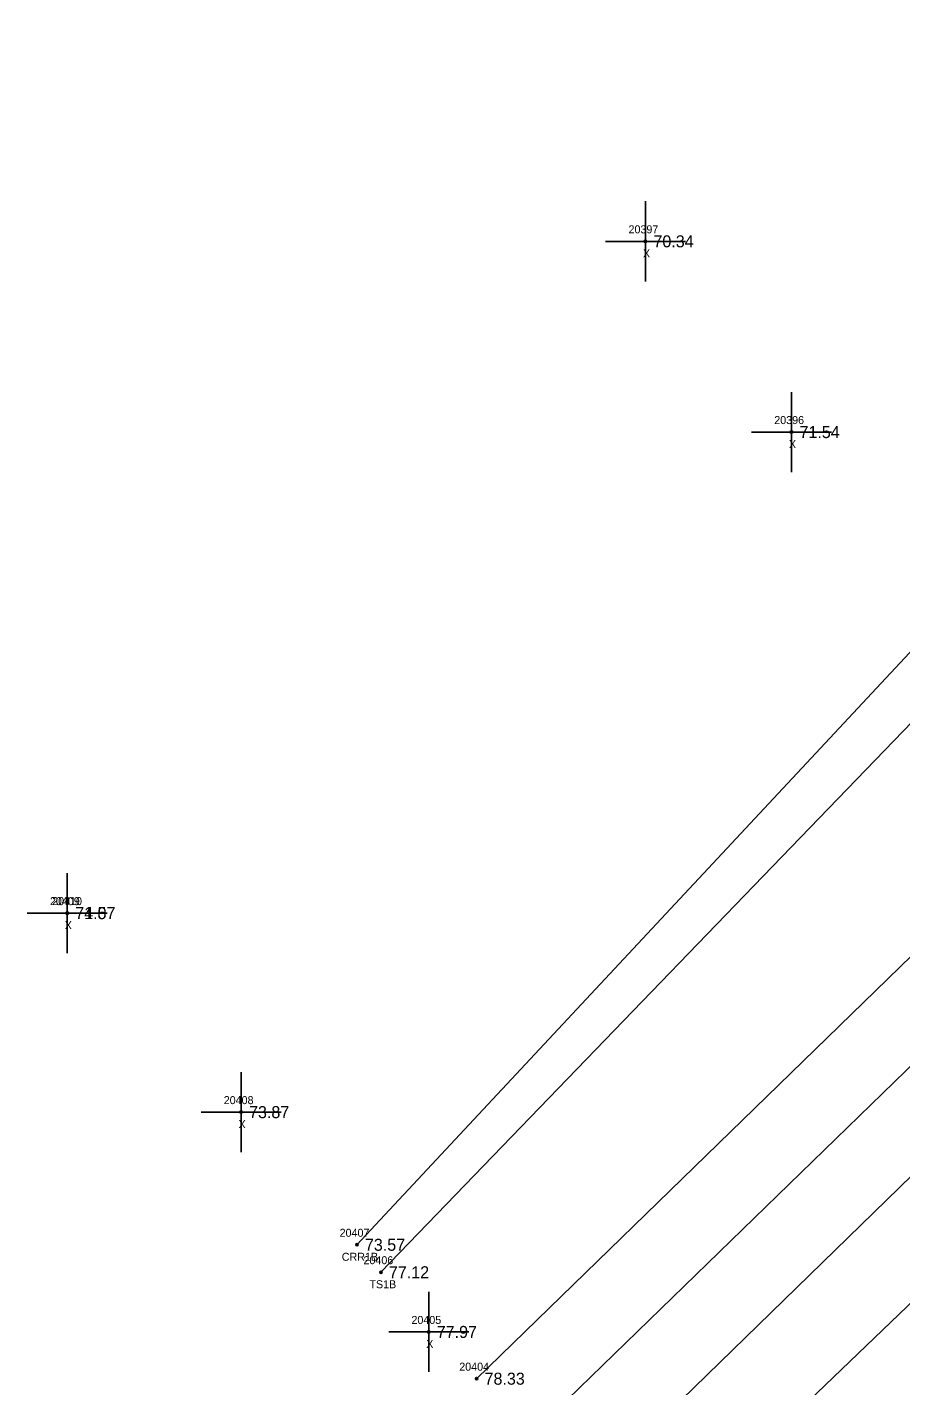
# Model space of a CAD drawing. Extents: x 2505300 to 2506184, y 912965 to 913825.
# Drawn here: x 2505300.1 to 2505409.2, y 913054.5 to 913224.2 of the extents above; entities that cross this region are included whole.
import ezdxf

# ---------------------------------------------------------------- set-up
doc = ezdxf.new("R2010")
doc.units = 0
for name, color, linetype in [('RD_DTM_BkLn1', 7, 'Continuous'), ('RD_DTM_BkLn2', 7, 'Continuous'), ('RD_DTM_BkLn_txCode', 7, 'Continuous'), ('RD_EX_H2O', 7, 'Continuous'), ('RD_EX_H2O_txCode', 7, 'Continuous'), ('RD_EX_Misc', 7, 'Continuous'), ('RD_EX_Misc_txCode', 7, 'Continuous'), ('RD_EX_Road', 7, 'Continuous'), ('RD_EX_Road_txCode', 7, 'Continuous'), ('RD_EX_TX_H2O_ELEV', 7, 'Continuous'), ('RD_EX_TX_Misc_ELEV', 7, 'Continuous'), ('RD_EX_TX_Road_ELEV', 7, 'Continuous'), ('RD_SMD_Locator', 7, 'Continuous')]:
    doc.layers.add(name, color=color, linetype=linetype)

msp = doc.modelspace()

# ---------------------------------------------------------------- linework, layer by layer
at = {"layer": 'RD_DTM_BkLn1'}
msp.add_lwpolyline([(2505767.92, 913463.52), (2505733.49, 913421.6), (2505698.21, 913380.67), (2505657.08, 913336.16), (2505615.28, 913294.08), (2505578.04, 913257.66), (2505509.81, 913190.87), (2505437.56, 913120.73), (2505363.23, 913048.54)], dxfattribs=at)
at = {"layer": 'RD_DTM_BkLn2'}
for points in [[(2505753.71, 913473.94), (2505744.94, 913478.08), (2505723.86, 913460.1), (2505705.31, 913435.28), (2505675.97, 913399.31), (2505635.15, 913352.85), (2505596.03, 913310.85), (2505561.37, 913275.87), (2505492.57, 913207.56), (2505417.69, 913144.74), (2505344.31, 913068.67)], [(2505608.57, 913197.02), (2505580.09, 913207.47), (2505555.7, 913208.91), (2505524.48, 913174.98), (2505452.19, 913104.88), (2505378.2, 913033.83)]]:
    msp.add_lwpolyline(points, dxfattribs=at)
at = {"layer": 'RD_EX_H2O'}
msp.add_lwpolyline([(2505789.47, 913464.31), (2505758.18, 913486.1), (2505736.66, 913480.49), (2505719.32, 913463.86), (2505699.9, 913439.21), (2505669.03, 913402.75), (2505628.5, 913357.9), (2505593, 913316.39), (2505556.58, 913279.8), (2505487.72, 913211.38), (2505413.81, 913149.81), (2505341.31, 913072.1)], dxfattribs=at)
at = {"layer": 'RD_EX_Misc'}
for p, q in [((2505377.34, 913192.46), (2505377.34, 913202.46)), ((2505372.34, 913197.46), (2505382.34, 913197.46)), ((2505395.58, 913168.63), (2505395.58, 913178.63)), ((2505390.58, 913173.63), (2505400.58, 913173.63)), ((2505305.13, 913108.53), (2505305.13, 913118.53)), ((2505305.13, 913108.53), (2505305.13, 913118.53)), ((2505300.13, 913113.53), (2505310.13, 913113.53)), ((2505300.13, 913113.53), (2505310.13, 913113.53)), ((2505326.84, 913083.67), (2505326.84, 913093.67)), ((2505321.84, 913088.67), (2505331.84, 913088.67)), ((2505350.28, 913056.21), (2505350.28, 913066.21)), ((2505345.28, 913061.21), (2505355.28, 913061.21))]:
    msp.add_line(p, q, dxfattribs=at)
at = {"layer": 'RD_EX_Road'}
for points in [[(2505758.23, 913470.96), (2505754.11, 913462.85), (2505725.4, 913427.85), (2505690.77, 913387.11), (2505650.25, 913343.36), (2505607.72, 913300.12), (2505570.97, 913264.99), (2505501.53, 913196.72), (2505431.76, 913128.83), (2505356.25, 913055.37)], [(2505777.56, 913455.88), (2505770.31, 913449.85), (2505741, 913414.45), (2505705.55, 913374.27), (2505664.83, 913329.82), (2505624.02, 913288.23), (2505585.62, 913250.63), (2505516.95, 913183.5), (2505444.27, 913113.56), (2505370.6, 913041.78)]]:
    msp.add_lwpolyline(points, dxfattribs=at)
at = {"layer": 'RD_SMD_Locator'}
for centre in [(2505377.34, 913197.46), (2505395.58, 913173.63), (2505305.13, 913113.53), (2505305.13, 913113.53), (2505326.84, 913088.67), (2505341.31, 913072.1), (2505344.31, 913068.67), (2505350.28, 913061.21), (2505356.25, 913055.37)]:
    msp.add_circle(centre, 0.15, dxfattribs=at)

# ---------------------------------------------------------------- texts
at = {"layer": 'RD_DTM_BkLn_txCode'}
for s, p in [('20406', (2505342.13, 913069.67)), ('TS1B', (2505342.87, 913066.67))]:
    msp.add_text(s, height=1, dxfattribs=at).set_placement(p)
at = {"layer": 'RD_EX_H2O_txCode'}
for s, p in [('20407', (2505339.15, 913073.1)), ('CRR1B', (2505339.42, 913070.1))]:
    msp.add_text(s, height=1, dxfattribs=at).set_placement(p)
at = {"layer": 'RD_EX_Misc_txCode'}
for s, p in [('20397', (2505375.23, 913198.46)), ('X', (2505377.03, 913195.46)), ('20396', (2505393.43, 913174.63)), ('X', (2505395.26, 913171.63)), ('20409', (2505302.98, 913114.53)), ('20410', (2505303.26, 913114.53)), ('X', (2505304.82, 913111.53)), ('X', (2505304.82, 913111.53)), ('20408', (2505324.68, 913089.67)), ('X', (2505326.52, 913086.67)), ('20405', (2505348.12, 913062.21)), ('X', (2505349.97, 913059.21))]:
    msp.add_text(s, height=1, dxfattribs=at).set_placement(p)
at = {"layer": 'RD_EX_Road_txCode'}
msp.add_text('20404', height=1, dxfattribs=at).set_placement((2505354.09, 913056.37))
at = {"layer": 'RD_EX_TX_H2O_ELEV'}
msp.add_text('73.57', height=1.5, dxfattribs=at).set_placement((2505342.31, 913071.35))
at = {"layer": 'RD_EX_TX_Misc_ELEV'}
for s, p in [('70.34', (2505378.34, 913196.71)), ('71.54', (2505396.58, 913172.88)), ('74.07', (2505306.13, 913112.78)), ('71.57', (2505306.13, 913112.78)), ('73.87', (2505327.84, 913087.92)), ('77.12', (2505345.31, 913067.92)), ('77.97', (2505351.28, 913060.46))]:
    msp.add_text(s, height=1.5, dxfattribs=at).set_placement(p)
at = {"layer": 'RD_EX_TX_Road_ELEV'}
msp.add_text('78.33', height=1.5, dxfattribs=at).set_placement((2505357.25, 913054.62))

doc.saveas('drawing.dxf')
